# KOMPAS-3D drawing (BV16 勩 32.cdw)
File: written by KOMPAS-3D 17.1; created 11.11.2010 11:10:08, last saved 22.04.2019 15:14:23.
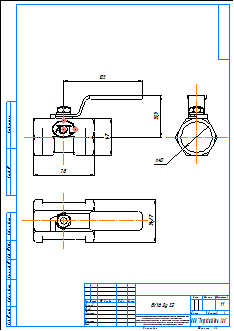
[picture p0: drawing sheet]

Sheet 1: A3, portrait

Title block, sheet 1: name: BV16 Ду 32; material: Внимание! Данный продукт является объектом авторского права ООО «Торговый Дом АДЛ». / Запрещается изменение, копирование, распространение / (в том числе путем копирования на другие сайты и ресурсы в Интернете) / или любое иное использование информации и объектов без предварительного / согласия правообладателя (ООО «Торговый Дом АДЛ»).; scale: 1:1; sheets: 1; organisation: ООО "Торговый дом АДЛ"; sheet format: A3; stored path: \\adlc.lan\data\АДЛ_ПКД\3D-модели\ADL production\Краны шаровые серии BV\BV16\KOMPAS 2D\BV16 Ду 32.cdw

Views: Спереди 1, Проекционный вид 2, Проекционный вид 3
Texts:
  user
  adl
Dimensions and other numbers on the sheet: 78; 47; 53,5; 103; 40; 54,27; 1:1; 1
